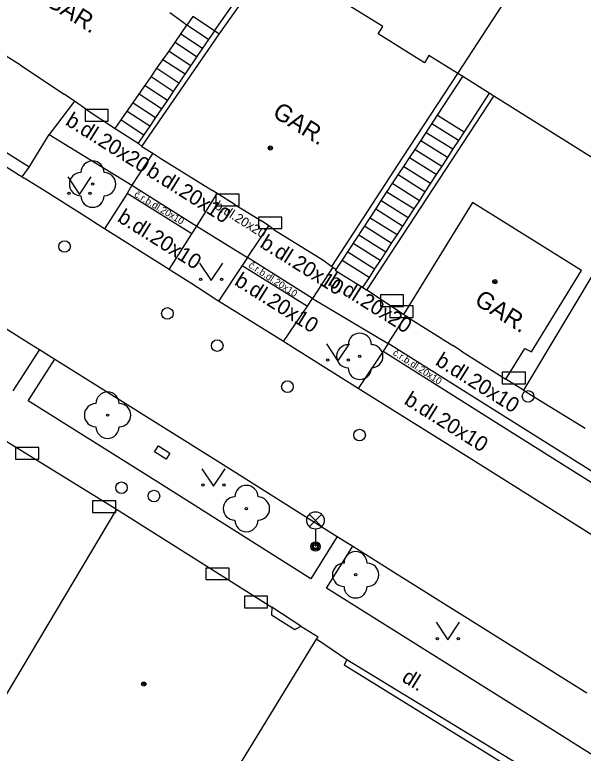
# Model space of a CAD drawing. Extents: x -595546 to -593986, y -1160845 to -1159202.
# Drawn here: x -595012.16 to -594987.64, y -1160748.75 to -1160716.88 of the extents above; entities that cross this region are included whole.
import ezdxf

# ---------------------------------------------------------------- set-up
doc = ezdxf.new("R2010")
doc.units = 0
for name, color, linetype in [('Level 22', 7, 'Continuous'), ('Level 24', 7, 'Continuous'), ('Level 28', 7, 'Continuous'), ('Level 33', 7, 'Continuous'), ('Level 36', 7, 'Continuous'), ('Level 39', 7, 'Continuous'), ('slaboproud - povrch.  znaky a tel. budka skut. velikost', 7, 'Continuous'), ('TM - budovy zdene_ betonove - NP', 7, 'Continuous'), ('TM - budovy zdene_ betonove - VP', 7, 'Continuous'), ('TM - chodniky - VP', 7, 'Continuous'), ('TM - komunikace - VP', 7, 'Continuous'), ('TM - plot drateny_ kovovy - VP', 7, 'Continuous'), ('TM - plot zdeny_ ohradni zed - VP', 7, 'Continuous'), ('TM - podezdivka plotu - VP', 7, 'Continuous'), ('TM - pomocna konstrukcni linie', 7, 'Continuous'), ('TM - popis objektu', 7, 'Continuous'), ('TM - popis povrchu', 7, 'Continuous'), ('TM - rozhrani mezi zpev. plochami mezi sebou - VP', 7, 'Continuous'), ('TM - rozhrani ploch obecne - VP', 7, 'Continuous'), ('TM - schody - VP', 7, 'Continuous'), ('TM - vjezd na pozemek', 7, 'Continuous'), ('TM - vstup do budovy - zdene_ betonove', 7, 'Continuous'), ('TM - vstup do budovy - zdene_ betonove  - shora neviditelny', 7, 'Continuous'), ('TM - zed operna - VP', 7, 'Continuous')]:
    doc.layers.add(name, color=color, linetype=linetype)

msp = doc.modelspace()

# ---------------------------------------------------------------- linework, layer by layer
at = {"layer": 'Level 22'}
for centre in [(-595008.81, -1160724.19), (-594997.28, -1160731.62), (-595008.16, -1160734.16), (-595002.17, -1160738.19), (-594997.46, -1160741.05)]:
    msp.add_circle(centre, 0.05, dxfattribs=at)
for centre, start, end in [((-595008.81, -1160723.69), 0, 180), ((-595009.31, -1160724.19), 90, 270), ((-595008.31, -1160724.19), 270, 90), ((-595008.81, -1160724.69), 180, 0), ((-594997.28, -1160731.12), 0, 180), ((-594997.78, -1160731.62), 90, 270), ((-594996.78, -1160731.62), 270, 90), ((-594997.28, -1160732.12), 180, 0), ((-595008.16, -1160733.66), 0, 180), ((-595008.66, -1160734.16), 90, 270), ((-595007.66, -1160734.16), 270, 90), ((-595008.16, -1160734.66), 180, 0), ((-595002.17, -1160737.69), 0, 180), ((-595002.67, -1160738.19), 90, 270), ((-595001.67, -1160738.19), 270, 90), ((-595002.17, -1160738.69), 180, 0), ((-594997.46, -1160740.55), 0, 180), ((-594997.96, -1160741.05), 90, 270), ((-594996.96, -1160741.05), 270, 90), ((-594997.46, -1160741.55), 180, 0)]:
    msp.add_arc(centre, 0.5, start, end, dxfattribs=at)
at = {"layer": 'Level 24'}
for points in [[(-595009.128, -1160721.469), (-595008.128, -1160721.469), (-595008.128, -1160720.969), (-595009.128, -1160720.969)], [(-595003.488, -1160725.119), (-595002.488, -1160725.119), (-595002.488, -1160724.619), (-595003.488, -1160724.619)], [(-595001.647, -1160726.108), (-595000.647, -1160726.108), (-595000.647, -1160725.608), (-595001.647, -1160725.608)], [(-594996.387, -1160729.468), (-594995.387, -1160729.468), (-594995.387, -1160728.968), (-594996.387, -1160728.968)], [(-594995.978, -1160729.939), (-594994.978, -1160729.939), (-594994.978, -1160729.439), (-594995.978, -1160729.439)], [(-594991.137, -1160732.808), (-594990.137, -1160732.808), (-594990.137, -1160732.308), (-594991.137, -1160732.308)], [(-595012.128, -1160736.059), (-595011.128, -1160736.059), (-595011.128, -1160735.559), (-595012.128, -1160735.559)], [(-595008.807, -1160738.358), (-595007.807, -1160738.358), (-595007.807, -1160737.858), (-595008.807, -1160737.858)], [(-595003.918, -1160741.259), (-595002.918, -1160741.259), (-595002.918, -1160740.759), (-595003.918, -1160740.759)], [(-595002.257, -1160742.478), (-595001.257, -1160742.478), (-595001.257, -1160741.978), (-595002.257, -1160741.978)]]:
    msp.add_lwpolyline(points, close=True, dxfattribs=at)
at = {"layer": 'Level 28'}
for centre in [(-595010.02, -1160726.88), (-595005.58, -1160729.77), (-595003.43, -1160731.16), (-595000.4, -1160732.93), (-594990.02, -1160733.35), (-594997.29, -1160735.02), (-595007.56, -1160737.29), (-595006.16, -1160737.65)]:
    msp.add_circle(centre, 0.25, dxfattribs=at)
at = {"layer": 'Level 33'}
for p, q in [((-594999.455, -1160738.97), (-594998.925, -1160738.44)), ((-594999.455, -1160738.44), (-594998.925, -1160738.97)), ((-594999.19, -1160739.08), (-594999.19, -1160739.83))]:
    msp.add_line(p, q, dxfattribs=at)
for centre, radius in [((-594999.19, -1160738.705), 0.375), ((-594999.19, -1160739.83), 0.2), ((-594999.19, -1160739.83), 0.145), ((-594999.19, -1160739.83), 0.0876)]:
    msp.add_circle(centre, radius, dxfattribs=at)
at = {"layer": 'Level 36'}
for points in [[(-595009.87, -1160723.88), (-595009.37, -1160724.63), (-595008.87, -1160723.88)], [(-595004.19, -1160727.6), (-595003.69, -1160728.35), (-595003.19, -1160727.6)], [(-594998.72, -1160731.08), (-594998.22, -1160731.83), (-594997.72, -1160731.08)], [(-595004.09, -1160736.48), (-595003.59, -1160737.23), (-595003.09, -1160736.48)], [(-594993.98, -1160743.1), (-594993.48, -1160743.85), (-594992.98, -1160743.1)]]:
    msp.add_lwpolyline(points, dxfattribs=at)
for centre in [(-595009.82, -1160724.58), (-595008.921, -1160724.58), (-595004.14, -1160728.3), (-595003.241, -1160728.3), (-594998.67, -1160731.78), (-594997.771, -1160731.78), (-595004.04, -1160737.18), (-595003.141, -1160737.18), (-594993.93, -1160743.8), (-594993.031, -1160743.8)]:
    msp.add_circle(centre, 0.05, dxfattribs=at)
at = {"layer": 'Level 39'}
for centre, radius in [((-595001.14, -1160722.63), 0.09), ((-595001.14, -1160722.63), 0.0398), ((-594991.45, -1160728.4), 0.09), ((-594991.45, -1160728.4), 0.0398), ((-595006.6, -1160745.76), 0.09), ((-595006.6, -1160745.76), 0.0398)]:
    msp.add_circle(centre, radius, dxfattribs=at)
at = {"layer": 'slaboproud - povrch.  znaky a tel. budka skut. velikost'}
msp.add_lwpolyline([(-595005.47, -1160735.8), (-595005.63, -1160736.06), (-595006.13, -1160735.74), (-595005.97, -1160735.48), (-595005.47, -1160735.8)], dxfattribs=at)
at = {"layer": 'TM - budovy zdene_ betonove - NP'}
for points in [[(-595001.08, -1160742.45), (-595001.09, -1160742.77)], [(-595000.08, -1160743.41), (-594999.82, -1160743.27)]]:
    msp.add_lwpolyline(points, dxfattribs=at)
at = {"layer": 'TM - budovy zdene_ betonove - VP'}
for points in [[(-595003.34, -1160717.72), (-595001.03, -1160714.43)], [(-594993.05, -1160719.41), (-594989.78, -1160714.4)], [(-594996.29, -1160717.39), (-594997.89, -1160716.39)], [(-595004.74, -1160717.33), (-595005.47, -1160716.8)], [(-595007.83, -1160721.79), (-595007.57, -1160721.42), (-595006.28, -1160719.56), (-595006.03, -1160719.19), (-595005.77, -1160718.82), (-595005.51, -1160718.45), (-595004.74, -1160717.33)], [(-594996.49, -1160717.7), (-594996.29, -1160717.39)], [(-595011.92, -1160719.06), (-595014.22, -1160717.61)], [(-595006.68, -1160722.56), (-595003.34, -1160717.72)], [(-594994.49, -1160718.95), (-594996.49, -1160717.7)], [(-594994.3, -1160718.64), (-594994.49, -1160718.95)], [(-594993.05, -1160719.41), (-594994.3, -1160718.64)], [(-594995.41, -1160723.01), (-594993.05, -1160719.41)], [(-594992.84, -1160719.54), (-594993.05, -1160719.41)], [(-594991.7, -1160720.26), (-594992.84, -1160719.54)], [(-595009.59, -1160720.61), (-595010.04, -1160720.3)], [(-594991.49, -1160720.39), (-594991.7, -1160720.26)], [(-595009.05, -1160720.98), (-595009.59, -1160720.61)], [(-594996.97, -1160728.76), (-594991.49, -1160720.39)], [(-594985.04, -1160724.43), (-594991.49, -1160720.39)], [(-595009.05, -1160720.98), (-595007.83, -1160721.79)], [(-595006.68, -1160722.56), (-595006.21, -1160722.86)], [(-595006.21, -1160722.86), (-595005.86, -1160723.08)], [(-594998.48, -1160727.74), (-594995.41, -1160723.01)], [(-595003.43, -1160724.59), (-595003.63, -1160724.46)], [(-594985.04, -1160724.43), (-594990.21, -1160733.08)], [(-595002.7, -1160725.06), (-595003.43, -1160724.59)], [(-594992.41, -1160724.98), (-594995.39, -1160729.81)], [(-594987.72, -1160727.91), (-594992.41, -1160724.98)], [(-595001.21, -1160725.99), (-595001.52, -1160725.78)], [(-595000.97, -1160726.16), (-595001.21, -1160725.99)], [(-594998.87, -1160727.46), (-594998.48, -1160727.74)], [(-594989.87, -1160731.42), (-594987.72, -1160727.91)], [(-594995.39, -1160729.81), (-594996.97, -1160728.76)], [(-594995.29, -1160729.88), (-594995.39, -1160729.81)], [(-594995.19, -1160729.95), (-594995.29, -1160729.88)], [(-594992.89, -1160731.4), (-594993.27, -1160731.16)], [(-594990.16, -1160731.28), (-594989.87, -1160731.42)], [(-594990.21, -1160733.08), (-594990.98, -1160732.6)], [(-594990.21, -1160733.08), (-594989.52, -1160733.51)], [(-595012.51, -1160735.29), (-595007.78, -1160738.22)], [(-595007.78, -1160738.22), (-595014.08, -1160748.77)], [(-595007.78, -1160738.22), (-595001.08, -1160742.45)], [(-594999.82, -1160743.27), (-595001.08, -1160742.45)], [(-594999.82, -1160743.27), (-594999.08, -1160743.72)], [(-595004.03, -1160751.82), (-594999.15, -1160743.83)], [(-594999.15, -1160743.83), (-594999.08, -1160743.72)]]:
    msp.add_lwpolyline(points, dxfattribs=at)
at = {"layer": 'TM - chodniky - VP'}
for points in [[(-595011.55, -1160723.45), (-595010.68, -1160722.05)], [(-595010.68, -1160722.05), (-595007.11, -1160724.23)], [(-595011.85, -1160723.88), (-595011.55, -1160723.45)], [(-595007.11, -1160724.23), (-595007.32, -1160724.59)], [(-595007.32, -1160724.59), (-595008.3, -1160726.12)], [(-595004.52, -1160726.34), (-595004.31, -1160726)], [(-595004.31, -1160726), (-595002.12, -1160727.36)], [(-595005.5, -1160727.88), (-595004.52, -1160726.34)], [(-595002.12, -1160727.36), (-595002.35, -1160727.7)], [(-595002.35, -1160727.7), (-595003.37, -1160729.24)], [(-594999.54, -1160729.45), (-594999.32, -1160729.12)], [(-594999.32, -1160729.12), (-594996.05, -1160731.06)], [(-595000.57, -1160730.98), (-594999.54, -1160729.45)], [(-594996.05, -1160731.06), (-594996.27, -1160731.4)], [(-595011.1, -1160731.33), (-595012.25, -1160733.11)], [(-594996.27, -1160731.4), (-594997.35, -1160733.01)], [(-595011.58, -1160733.54), (-595010.43, -1160731.75)], [(-595005.88, -1160737.13), (-595011.58, -1160733.54)], [(-594999.39, -1160741.22), (-595005.88, -1160737.13)], [(-594998.25, -1160739.4), (-594999.39, -1160741.22)], [(-594998.72, -1160741.63), (-594997.58, -1160739.82)], [(-594989.04, -1160747.7), (-594998.72, -1160741.63)], [(-594975.82, -1160756.03), (-594989.04, -1160747.7)]]:
    msp.add_lwpolyline(points, dxfattribs=at)
at = {"layer": 'TM - komunikace - VP'}
for points in [[(-595020.07, -1160718.69), (-595011.85, -1160723.88)], [(-595011.85, -1160723.88), (-595011.76, -1160723.93)], [(-595010.9, -1160724.47), (-595011.76, -1160723.93)], [(-595009.22, -1160725.53), (-595010.9, -1160724.47)], [(-595008.37, -1160726.07), (-595009.22, -1160725.53)], [(-595008.3, -1160726.12), (-595008.37, -1160726.07)], [(-595005.5, -1160727.88), (-595008.3, -1160726.12)], [(-595005.42, -1160727.93), (-595005.5, -1160727.88)], [(-595004.57, -1160728.46), (-595005.42, -1160727.93)], [(-595004.28, -1160728.65), (-595004.57, -1160728.46)], [(-595003.44, -1160729.19), (-595004.28, -1160728.65)], [(-595014.6, -1160729.12), (-595011.54, -1160731.05)], [(-595003.37, -1160729.24), (-595003.44, -1160729.19)], [(-595000.57, -1160730.98), (-595003.37, -1160729.24)], [(-595011.54, -1160731.05), (-595011.1, -1160731.33)], [(-594997.35, -1160733.01), (-595000.48, -1160731.04), (-595000.57, -1160730.98)], [(-595011.1, -1160731.33), (-595010.43, -1160731.75)], [(-595010.43, -1160731.75), (-595003.29, -1160736.22)], [(-594992.45, -1160736.08), (-594997.35, -1160733.01)], [(-595003.29, -1160736.22), (-594998.25, -1160739.4)], [(-594984.46, -1160741.09), (-594992.45, -1160736.08)], [(-594998.25, -1160739.4), (-594997.58, -1160739.82)], [(-594997.58, -1160739.82), (-594995.67, -1160741.02)], [(-594995.67, -1160741.02), (-594987.49, -1160746.15)]]:
    msp.add_lwpolyline(points, dxfattribs=at)
at = {"layer": 'TM - plot drateny_ kovovy - VP'}
msp.add_lwpolyline([(-594997.95, -1160744.93), (-594990.91, -1160749.3)], dxfattribs=at)
at = {"layer": 'TM - plot zdeny_ ohradni zed - VP'}
for points in [[(-594998.48, -1160727.74), (-594998.44, -1160727.77)], [(-594998.44, -1160727.77), (-594998.3, -1160727.87)], [(-594998.3, -1160727.87), (-594998.34, -1160727.9)], [(-594998.34, -1160727.9), (-594998.1, -1160728.06)]]:
    msp.add_lwpolyline(points, dxfattribs=at)
at = {"layer": 'TM - podezdivka plotu - VP'}
for points in [[(-594997.84, -1160744.72), (-594997.95, -1160744.93)], [(-594990.48, -1160749.21), (-594997.84, -1160744.72)]]:
    msp.add_lwpolyline(points, dxfattribs=at)
at = {"layer": 'TM - pomocna konstrukcni linie'}
msp.add_lwpolyline([(-594990.98, -1160732.6), (-594990.16, -1160731.28)], dxfattribs=at)
at = {"layer": 'TM - rozhrani mezi zpev. plochami mezi sebou - VP'}
for points in [[(-595009.59, -1160720.61), (-595010.68, -1160722.05)], [(-595011.55, -1160723.45), (-595015.81, -1160720.75)], [(-595006.21, -1160722.86), (-595007.11, -1160724.23)], [(-595007.11, -1160724.23), (-595004.31, -1160726)], [(-595004.52, -1160726.34), (-595007.32, -1160724.59)], [(-595004.31, -1160726), (-595003.43, -1160724.59)], [(-595002.12, -1160727.36), (-595001.21, -1160725.99)], [(-594999.32, -1160729.12), (-595002.12, -1160727.36)], [(-595002.35, -1160727.7), (-594999.54, -1160729.45)], [(-594998.44, -1160727.77), (-594999.32, -1160729.12)], [(-594996.05, -1160731.06), (-594995.29, -1160729.88)], [(-594990.84, -1160734.35), (-594996.05, -1160731.06)], [(-594996.27, -1160731.4), (-594991.09, -1160734.66)], [(-594983.16, -1160739.16), (-594990.84, -1160734.35)], [(-594991.09, -1160734.66), (-594983.39, -1160739.51)]]:
    msp.add_lwpolyline(points, dxfattribs=at)
at = {"layer": 'TM - rozhrani ploch obecne - VP'}
for points in [[(-595003.55, -1160717.58), (-595004.48, -1160716.96), (-595004.74, -1160717.33)], [(-595003.55, -1160717.58), (-595003.8, -1160717.95), (-595004.06, -1160718.32), (-595005.33, -1160720.19), (-595005.58, -1160720.56), (-595005.84, -1160720.94), (-595006.09, -1160721.31), (-595006.34, -1160721.69), (-595006.6, -1160722.06), (-595006.84, -1160722.42)], [(-595003.34, -1160717.72), (-595003.55, -1160717.58)], [(-594993.93, -1160721.22), (-594992.84, -1160719.54)], [(-594991.7, -1160720.26), (-594992.78, -1160721.93)], [(-594998.3, -1160727.87), (-594998.04, -1160727.48), (-594996.83, -1160725.64), (-594996.59, -1160725.27), (-594996.35, -1160724.9), (-594995.62, -1160723.79), (-594995.38, -1160723.43), (-594995.14, -1160723.06), (-594994.89, -1160722.69), (-594994.65, -1160722.32), (-594993.93, -1160721.22)], [(-594992.78, -1160721.93), (-594993.02, -1160722.3), (-594993.26, -1160722.67), (-594993.5, -1160723.04), (-594993.74, -1160723.41), (-594993.99, -1160723.78), (-594994.23, -1160724.15), (-594994.47, -1160724.52), (-594994.71, -1160724.89), (-594994.95, -1160725.26), (-594995.19, -1160725.63), (-594995.43, -1160726), (-594995.67, -1160726.37), (-594995.92, -1160726.74), (-594996.16, -1160727.11), (-594996.4, -1160727.48), (-594996.64, -1160727.85), (-594996.88, -1160728.22), (-594997.16, -1160728.64)], [(-594999.15, -1160743.83), (-594999.1, -1160743.86)]]:
    msp.add_lwpolyline(points, dxfattribs=at)
at = {"layer": 'TM - schody - VP'}
for points in [[(-595003.8, -1160717.95), (-595004.74, -1160717.33)], [(-595005, -1160717.7), (-595004.06, -1160718.32)], [(-595004.32, -1160718.7), (-595005.25, -1160718.08)], [(-595005.51, -1160718.45), (-595004.57, -1160719.07)], [(-595004.82, -1160719.44), (-595005.77, -1160718.82)], [(-595006.03, -1160719.19), (-595005.08, -1160719.82)], [(-595005.33, -1160720.19), (-595006.28, -1160719.56)], [(-595006.54, -1160719.93), (-595005.58, -1160720.56)], [(-595005.84, -1160720.94), (-595006.8, -1160720.3)], [(-595007.06, -1160720.68), (-595006.09, -1160721.31)], [(-595006.34, -1160721.69), (-595007.31, -1160721.05)], [(-594993.93, -1160721.22), (-594992.78, -1160721.93)], [(-595007.57, -1160721.42), (-595006.6, -1160722.06)], [(-594993.02, -1160722.3), (-594994.17, -1160721.59)], [(-594994.41, -1160721.96), (-594993.26, -1160722.67)], [(-594993.5, -1160723.04), (-594994.65, -1160722.32)], [(-594994.89, -1160722.69), (-594993.74, -1160723.41)], [(-594993.99, -1160723.78), (-594995.14, -1160723.06)], [(-594995.38, -1160723.43), (-594994.23, -1160724.15)], [(-594994.47, -1160724.52), (-594995.62, -1160723.79)], [(-594995.86, -1160724.16), (-594994.71, -1160724.89)], [(-594994.95, -1160725.26), (-594996.11, -1160724.54)], [(-594996.35, -1160724.9), (-594995.19, -1160725.63)], [(-594995.43, -1160726), (-594996.59, -1160725.27)], [(-594996.83, -1160725.64), (-594995.67, -1160726.37)], [(-594995.92, -1160726.74), (-594997.08, -1160726.01)], [(-594997.32, -1160726.38), (-594996.16, -1160727.11)], [(-594996.4, -1160727.48), (-594997.56, -1160726.75)], [(-594997.8, -1160727.11), (-594996.64, -1160727.85)], [(-594996.88, -1160728.22), (-594998.04, -1160727.48)]]:
    msp.add_lwpolyline(points, dxfattribs=at)
at = {"layer": 'TM - vjezd na pozemek'}
for points in [[(-595007.83, -1160721.79), (-595006.84, -1160722.42)], [(-594997.84, -1160744.72), (-594999.1, -1160743.86)]]:
    msp.add_lwpolyline(points, dxfattribs=at)
at = {"layer": 'TM - vstup do budovy - zdene_ betonove'}
for points in [[(-595011.92, -1160719.06), (-595010.04, -1160720.3)], [(-595005.86, -1160723.08), (-595003.63, -1160724.46)], [(-595002.7, -1160725.06), (-595001.52, -1160725.78)], [(-595000.97, -1160726.16), (-594998.87, -1160727.46)], [(-594998.1, -1160728.06), (-594997.16, -1160728.64)], [(-594997.16, -1160728.64), (-594996.97, -1160728.76)], [(-594995.19, -1160729.95), (-594993.27, -1160731.16)], [(-594992.89, -1160731.4), (-594990.98, -1160732.6)], [(-594989.52, -1160733.51), (-594987.56, -1160734.72)]]:
    msp.add_lwpolyline(points, dxfattribs=at)
at = {"layer": 'TM - vstup do budovy - zdene_ betonove  - shora neviditelny'}
msp.add_lwpolyline([(-595001.09, -1160742.77), (-595000.08, -1160743.41)], dxfattribs=at)
at = {"layer": 'TM - zed operna - VP'}
for points in [[(-595003.55, -1160717.58), (-595001.73, -1160714.99)], [(-595006.84, -1160722.42), (-595006.68, -1160722.56)]]:
    msp.add_lwpolyline(points, dxfattribs=at)

# ---------------------------------------------------------------- texts
at = {"layer": 'TM - popis objektu'}
for rotation, p in [(327.93, (-595010.92, -1160716.41)), (327.93, (-595001.09, -1160721.24)), (328.1, (-594992.38, -1160729.34))]:
    msp.add_text('GAR.', height=0.75, rotation=rotation, dxfattribs=at).set_placement(p)
at = {"layer": 'TM - popis povrchu'}
for s, height, rotation, p in [('b.dl.20x20', 0.65, 327.9101, (-595010.02, -1160721.6)), ('b.dl.20x10', 0.65, 327.9101, (-595006.53, -1160723.78)), ('č.r.b.dl.20x10', 0.3, 328.9582, (-595007.04, -1160724.71)), ('b.dl.20x20', 0.4, 327.9101, (-595003.57, -1160725.22)), ('b.dl.20x10', 0.65, 327.9101, (-595007.78, -1160725.77)), ('b.dl.20x10', 0.65, 327.9101, (-595001.63, -1160726.88)), ('č.r.b.dl.20x10', 0.3, 326.8134, (-595002.11, -1160727.76)), ('b.dl.20x10', 0.65, 327.9101, (-595002.73, -1160728.51)), ('b.dl.20x20', 0.65, 327.9101, (-594998.7, -1160728.52)), ('č.r.b.dl.20x10', 0.3, 326.8134, (-594995.88, -1160731.54)), ('b.dl.20x10', 0.65, 327.9101, (-594994.06, -1160731.96)), ('b.dl.20x10', 0.65, 327.9101, (-594995.41, -1160733.65)), ('dl.', 0.65, 328.1492, (-594995.51, -1160745.62))]:
    msp.add_text(s, height=height, rotation=rotation, dxfattribs=at).set_placement(p)

doc.saveas('drawing.dxf')
